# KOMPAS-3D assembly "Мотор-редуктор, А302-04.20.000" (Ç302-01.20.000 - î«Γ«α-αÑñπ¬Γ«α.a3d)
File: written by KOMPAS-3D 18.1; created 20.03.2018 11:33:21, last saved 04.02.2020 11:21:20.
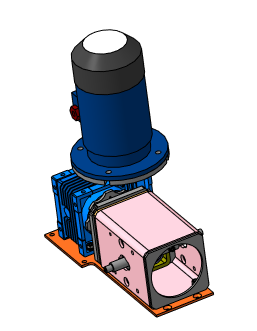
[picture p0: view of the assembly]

Document properties: Автор: Милов; Полное имя файла: D:\Мембранные насосы\Мембранный электропривод\А302-00.00.000 - ASTRA-302 (МЭ200) новая для Караби\3Д ПВХ\Отработка\А302-01.20.000 - Мотор-редуктор.a3d

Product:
- Part/product: Мотор-редуктор  | designation А302-04.20.000  | pos. 0
    Масса: 34.037
    Раздел спецификации: Сборочные единицы
    Форматы листов документа: 2xA3
    Примечание: @100~)2xA3
    source file: ..\..\А302-04.00.000 - Мембранный насос ASTRA-302-PP\А302-04.20.000 СБ - Мотор-редуктор.cdw
  - Component [standard]: Винт с цилиндрической головкой и шестигранным углублением под ключ ГОСТ Р ИСО 4762-М8 x 25-A2-70  | pos. 150  | Материал: Нержавеющая сталь (density 1000 kg/m3); Масса: 0.015; Раздел спецификации: Стандартные изделия; Рассекать на разрезах: no; additional columns: ГОСТ Р ИСО 4762-2012; М8 x 25 - A2-70
  - Component [standard]: Винт с цилиндрической головкой и шестигранным углублением под ключ ГОСТ Р ИСО 4762-М8 x 25-A2-70  | pos. 149  | Материал: Нержавеющая сталь (density 1000 kg/m3); Масса: 0.015; Раздел спецификации: Стандартные изделия; Рассекать на разрезах: no; additional columns: ГОСТ Р ИСО 4762-2012; М8 x 25 - A2-70
  - Component [standard]: Винт с цилиндрической головкой и шестигранным углублением под ключ ГОСТ Р ИСО 4762-М8 x 25-A2-70  | pos. 147  | Материал: Нержавеющая сталь (density 1000 kg/m3); Масса: 0.015; Раздел спецификации: Стандартные изделия; Рассекать на разрезах: no; additional columns: ГОСТ Р ИСО 4762-2012; М8 x 25 - A2-70
  - Component [standard]: Винт с цилиндрической головкой и шестигранным углублением под ключ ГОСТ Р ИСО 4762-М8 x 25-A2-70  | pos. 146  | Материал: Нержавеющая сталь (density 1000 kg/m3); Масса: 0.015; Раздел спецификации: Стандартные изделия; Рассекать на разрезах: no; additional columns: ГОСТ Р ИСО 4762-2012; М8 x 25 - A2-70
  - Component [standard]: Винт с цилиндрической головкой и шестигранным углублением под ключ ГОСТ Р ИСО 4762-М8 x 25-A2-70  | pos. 140  | Материал: Нержавеющая сталь (density 1000 kg/m3); Масса: 0.015; Раздел спецификации: Стандартные изделия; Рассекать на разрезах: no; additional columns: ГОСТ Р ИСО 4762-2012; М8 x 25 - A2-70
  - Component [standard]: Винт с цилиндрической головкой и шестигранным углублением под ключ ГОСТ Р ИСО 4762-М8 x 25-A2-70  | pos. 139  | Материал: Нержавеющая сталь (density 1000 kg/m3); Масса: 0.015; Раздел спецификации: Стандартные изделия; Рассекать на разрезах: no; additional columns: ГОСТ Р ИСО 4762-2012; М8 x 25 - A2-70
  - Component [standard]: Винт с цилиндрической головкой и шестигранным углублением под ключ ГОСТ Р ИСО 4762-М8 x 25-A2-70  | pos. 138  | Материал: Нержавеющая сталь (density 1000 kg/m3); Масса: 0.015; Раздел спецификации: Стандартные изделия; Рассекать на разрезах: no; additional columns: ГОСТ Р ИСО 4762-2012; М8 x 25 - A2-70
  - Component [standard]: Винт с цилиндрической головкой и шестигранным углублением под ключ ГОСТ Р ИСО 4762-М8 x 25-A2-70  | pos. 137  | Материал: Нержавеющая сталь (density 1000 kg/m3); Масса: 0.015; Раздел спецификации: Стандартные изделия; Рассекать на разрезах: no; additional columns: ГОСТ Р ИСО 4762-2012; М8 x 25 - A2-70
  - Component [standard]: Винт с цилиндрической головкой и шестигранным углублением под ключ ГОСТ Р ИСО 4762-М8 x 25-A2-70  | pos. 129  | Материал: Нержавеющая сталь (density 1000 kg/m3); Масса: 0.015; Раздел спецификации: Стандартные изделия; Рассекать на разрезах: no; additional columns: ГОСТ Р ИСО 4762-2012; М8 x 25 - A2-70
  - Component [standard]: Винт с цилиндрической головкой и шестигранным углублением под ключ ГОСТ Р ИСО 4762-М8 x 25-A2-70  | pos. 128  | Материал: Нержавеющая сталь (density 1000 kg/m3); Масса: 0.015; Раздел спецификации: Стандартные изделия; Рассекать на разрезах: no; additional columns: ГОСТ Р ИСО 4762-2012; М8 x 25 - A2-70
  - Component [standard]: Гайка М6-6H.21.12Х18Н10Т ГОСТ 5915-70  | qty 2  | Материал: Сталь 12Х18Н10Т ГОСТ 5632-72 (density 1000 kg/m3); Масса: 0.002573; Раздел спецификации: Стандартные изделия; Рассекать на разрезах: no
  - Component [standard]: Шайба 6 30Х13 019 ГОСТ 6402-70  | qty 2  | Материал: Сталь 30Х13 ГОСТ 5632-72 (density 1000 kg/m3); Масса: 0.000376; Раздел спецификации: Стандартные изделия; Рассекать на разрезах: no
  - Component [standard]: Шайба C.6.21 ГОСТ 11371-78  | qty 3  | Материал: Сталь 12Х18Н10Т ГОСТ 5632-72 (density 1000 kg/m3); Масса: 0.00099; Раздел спецификации: Стандартные изделия; Рассекать на разрезах: no
  - Component [standard]: Болт М6-6gx40 ГОСТ 7805-70  | qty 2  | Масса: 0.0112; Раздел спецификации: Стандартные изделия; Рассекать на разрезах: no
  - Component [standard]: Шайба C.6.21 ГОСТ 11371-78  | Материал: Сталь 20 ГОСТ 1050-2013 (density 1000 kg/m3); Масса: 0.00043; Раздел спецификации: Стандартные изделия; Рассекать на разрезах: no
  - Component [detail]: Вал  | designation А302-04.20.004  | pos. 3
      Материал: Сталь 40Х  ГОСТ 4543-71 (density 7825 kg/m3)
      Масса: 0.49487
      Раздел спецификации: Детали
      Форматы листов документа: A3
      Примечание: Заим.
      source file: ..\..\3Д\А302-00.20.004 - Вал.m3d, ..\..\А302-04.00.000 - Мембранный насос ASTRA-302-PP\А302-04.20.004 - Вал.cdw, ..\..\Чертежи ПВХ\А302-03.20.004 - Вал.cdw
  - Component [detail]: Эксцентрик  | designation А302-01.20.002  | pos. 5  | Материал: Сталь 40Х  ГОСТ 4543-71 (density 7825 kg/m3); Масса: 1.91612; Раздел спецификации: Детали; Форматы листов документа: A3; source file: ..\А302-01.20.002 - Эксцентрик.cdw, ..\А302-01.20.002 - Эксцентрик.m3d
  - Component [assembly]: Фланец  | designation А302-04.35.000  | pos. 1  | Масса: 8.08129; Раздел спецификации: Сборочные единицы; Форматы листов документа: A2; source file: ..\..\А302-04.00.000 - Мембранный насос ASTRA-302-PP Чертежи\А302-04.35.000 - Фланец.cdw, ..\..\А302-04.00.000 - Мембранный насос ASTRA-302-PP\А302-04.35.000 - Фланец.cdw, ..\А302-01.35.000 - Фланец.a3d
  - Component [detail]: Основание  | designation А302-04.20.001  | pos. 4  | Материал: Сталь 20  ГОСТ 1050-2013 (density 7820 kg/m3); Масса: 2.48727; Раздел спецификации: Детали; Форматы листов документа: A3
  - Component [detail]: FB 063  | pos. 6  | Масса: 1.71461; Раздел спецификации: Детали; source file: ..\FB 063 .m3d
  - Component [detail]: Подшипник 80х40х18 6208-2RS1 SKF  | pos. 54  | Масса: 0.504792; Раздел спецификации: Стандартные изделия; source file: ..\..\..\..\..\1 ПКИ 3D\1 Крепеж стандартный\Подшипник\Подшипник 80х40х18 6208-2RS1 SKF.m3d
  - Component [standard]: Кольцо A40.65Г ГОСТ 13942-86  | pos. 51  | Материал: Сталь 65Г ГОСТ 14959-79 (density 1000 kg/m3); Масса: 0.007267; Раздел спецификации: Стандартные изделия; additional columns: Сталь 65Г ГОСТ 14959-79
- Part/product: Мотор-редуктор  | designation А302-02.20.000  | pos. 0
    Масса: 27.8186
    Раздел спецификации: Сборочные единицы
    Форматы листов документа: 2xA3
    Примечание: @100~)2xA3
  - Component [detail]: Основание  | designation А302-01.20.001  | pos. 4  | Материал: Сталь 20  ГОСТ 1050-2013 (density 7820 kg/m3); Масса: 2.48169; Раздел спецификации: Детали; Форматы листов документа: A3; source file: ..\..\А302-04.00.000 - Мембранный насос ASTRA-302-PP\А302-04.20.001 - Основание.cdw, ..\А302-01.20.001 - Основание.cdw, ..\А302-01.20.001 - Основание.m3d
  - Component [assembly]: Фланец  | designation А302-01.35.000  | pos. 1  | Масса: 8.26617; Раздел спецификации: Сборочные единицы; Форматы листов документа: 2xA3; Примечание: @100~)2xA3; source file: ..\А302-01.35.000 - Фланец.a3d, ..\А302-01.35.000 - Фланец.cdw
  - Component [detail]: Эксцентрик  | designation А302-01.20.002  | pos. 5  | Материал: Сталь 40Х  ГОСТ 4543-71 (density 7825 kg/m3); Масса: 1.91612; Раздел спецификации: Детали; Форматы листов документа: A3; source file: ..\А302-01.20.002 - Эксцентрик.cdw, ..\А302-01.20.002 - Эксцентрик.m3d
  - Component [detail]: Вал  | designation А302-04.20.004  | pos. 3
      Материал: Сталь 40Х  ГОСТ 4543-71 (density 7825 kg/m3)
      Масса: 0.49487
      Раздел спецификации: Детали
      Форматы листов документа: A3
      Примечание: Заим.
      source file: ..\..\3Д\А302-00.20.004 - Вал.m3d, ..\..\А302-04.00.000 - Мембранный насос ASTRA-302-PP\А302-04.20.004 - Вал.cdw, ..\..\Чертежи ПВХ\А302-03.20.004 - Вал.cdw
- Part/product: Мотор-редуктор  | designation А302-01.20.000  | pos. 0
    Масса: 27.8253
    Раздел спецификации: Сборочные единицы
    Форматы листов документа: 2xA3
    Примечание: @100~)2xA3
    source file: ..\А302-01.20.000 - Мотор-редуктор.cdw
  - Component [standard]: Гайка М8-6H.21.12Х18Н10Т ГОСТ 5915-70  | qty 6  | Материал: Сталь 12Х18Н10Т ГОСТ 5632-72 (density 1000 kg/m3); Масса: 0.005548; Раздел спецификации: Стандартные изделия; source file: C:\Program Files\ASCON\KOMPAS-3D v18\Libs\PartLib\DATA\VAULT\methods\kompas\3d\PLib_Nut_OST92_900.m3d
  - Component [standard]: Шайба C.8.21 ГОСТ 11371-78  | qty 8  | pos. 18  | Материал: Сталь 12Х18Н10Т ГОСТ 5632-72 (density 1000 kg/m3); Масса: 0.001725; Раздел спецификации: Стандартные изделия; additional columns: Сталь 12Х18Н10Т ГОСТ 5632-72; source file: C:\Program Files\ASCON\KOMPAS-3D v18\Libs\PartLib\DATA\VAULT\methods\kompas\3d\PLib_Washer_1_712.m3d
  - Component [standard]: Шайба 8 30Х13 019 ГОСТ 6402-70  | qty 14  | Материал: Сталь 30Х13 ГОСТ 5632-72 (density 1000 kg/m3); Масса: 0.001034; Раздел спецификации: Стандартные изделия; source file: C:\Program Files\ASCON\KOMPAS-3D v18\Libs\PartLib\DATA\VAULT\methods\kompas\3d\PLib_Washer_2_712.m3d
  - Component [standard]: Винт с цилиндрической головкой и шестигранным углублением под ключ ГОСТ Р ИСО 4762 - М8 x 25 - A2-70  | qty 10  | Материал: Нержавеющая сталь (density 1000 kg/m3); Масса: 0.015; Раздел спецификации: Стандартные изделия; additional columns: ГОСТ Р ИСО 4762-2012; source file: C:\Program Files\ASCON\KOMPAS-3D v18\Libs\PartLib\DATA\VAULT\methods\kompas\3d\PLib_Screw_DIN_7984_1500.m3d
  - Component [standard]: Шайба C.8.21 ГОСТ 11371-78  | qty 12  | Материал: Сталь 12Х18Н10Т ГОСТ 5632-72 (density 1000 kg/m3); Масса: 0.001725; Раздел спецификации: Стандартные изделия; source file: C:\Program Files\ASCON\KOMPAS-3D v18\Libs\PartLib\DATA\VAULT\methods\kompas\3d\PLib_Washer_1_712.m3d
  - Component [standard]: Шпонка 8x7x90 ГОСТ 23360-78  | Масса: 0.03854; Раздел спецификации: Стандартные изделия; source file: C:\Program Files\ASCON\KOMPAS-3D v18\Libs\PartLib\DATA\VAULT\methods\kompas\3d\PLib_Key_prismatic_712.m3d
  - Component [standard]: Винт с цилиндрической головкой и шестигранным углублением под ключ ГОСТ Р ИСО 4762 - М8 x 35 - A2-70  | qty 4  | Материал: Нержавеющая сталь (density 1000 kg/m3); Масса: 0.0189; Раздел спецификации: Стандартные изделия; additional columns: ГОСТ Р ИСО 4762-2012; source file: C:\Program Files\ASCON\KOMPAS-3D v18\Libs\PartLib\DATA\VAULT\methods\kompas\3d\PLib_Screw_DIN_7984_1500.m3d
  - Component [standard]: Гайка М5-6H.5.019 ГОСТ 5915-70  | qty 2  | Масса: 0.00144; Раздел спецификации: Стандартные изделия; source file: C:\Program Files\ASCON\KOMPAS-3D v18\Libs\PartLib\DATA\VAULT\methods\kompas\3d\PLib_Nut_OST92_900.m3d
  - Component [standard]: Шайба 5 30Х13 019 ГОСТ 6402-70  | qty 2  | Материал: Сталь 30Х13 ГОСТ 5632-72 (density 1000 kg/m3); Масса: 0.000228; Раздел спецификации: Стандартные изделия; source file: C:\Program Files\ASCON\KOMPAS-3D v18\Libs\PartLib\DATA\VAULT\methods\kompas\3d\PLib_Washer_2_712.m3d
  - Component [standard]: Шайба C.5.04.019 ГОСТ 11371-78  | qty 4  | Материал: Сталь 20 ГОСТ 1050-2013 (density 1000 kg/m3); Масса: 0.00043; Раздел спецификации: Стандартные изделия; source file: C:\Program Files\ASCON\KOMPAS-3D v18\Libs\PartLib\DATA\VAULT\methods\kompas\3d\PLib_Washer_1_712.m3d
  - Component [standard]: Болт М5-6gx35.58.019 ГОСТ 7805-70  | qty 2  | Материал: Сталь 20 ГОСТ 1050-2013 (density 1000 kg/m3); Масса: 0.006685; Раздел спецификации: Стандартные изделия; source file: C:\Program Files\ASCON\KOMPAS-3D v18\Libs\PartLib\DATA\VAULT\methods\kompas\3d\PLib_Bolt_1_900.m3d
  - Component [detail]: Ползун  | designation А302-00.20.003  | pos. 2
      Материал: Полиамид П-12Б-20  ТУ 6-05-898-73 (density 1020 kg/m3)
      Масса: 0.0527789
      Раздел спецификации: Детали
      Форматы листов документа: A3
      Примечание: Заим.
      source file: ..\..\3Д\А302-00.20.003 - Ползун.m3d
  - Component [detail]: Вал  | designation А302-02.20.004  | pos. 3
      Материал: Сталь 40Х  ГОСТ 4543-71 (density 7825 kg/m3)
      Масса: 0.365977
      Раздел спецификации: Детали
      Форматы листов документа: A3
      Примечание: Заим.
      source file: ..\..\3Д\А302-00.20.004 - Вал.m3d, ..\..\Чертежи ПВХ\А302-02.20.004 - Вал.cdw
  - Component [detail]: Подшипник 52х25х15 62052RSH SKF  | pos. 21  | Масса: 0.182287; Раздел спецификации: Стандартные изделия; source file: ..\..\..\..\..\1 ПКИ 3D\1 Крепеж стандартный\Подшипник\Подшипник 52х25х15 62052RSH SKF.m3d
  - Component [standard]: Кольцо A25.65Г ГОСТ 13942-86  | qty 3  | Материал: Сталь 65Г ГОСТ 14959-79 (density 1000 kg/m3); Масса: 0.002684; Раздел спецификации: Стандартные изделия; source file: C:\Program Files\ASCON\KOMPAS-3D v18\Libs\PartLib\DATA\VAULT\methods\kompas\3d\PLib_Check_spring_rings_GOST_13942_911.m3d
  - Component [detail]: Эксцентрик  | designation А302-01.20.002  | pos. 5  | Материал: Сталь 40Х  ГОСТ 4543-71 (density 7825 kg/m3); Масса: 1.91612; Раздел спецификации: Детали; Форматы листов документа: A3; source file: ..\А302-01.20.002 - Эксцентрик.cdw, ..\А302-01.20.002 - Эксцентрик.m3d
  - Component [assembly]: Фланец  | designation А302-01.35.000  | pos. 1  | Масса: 8.26617; Раздел спецификации: Сборочные единицы; Форматы листов документа: 2xA3; Примечание: @100~)2xA3; source file: ..\А302-01.35.000 - Фланец.a3d, ..\А302-01.35.000 - Фланец.cdw
  - Component [detail]: Основание  | designation А302-01.20.001  | pos. 4  | Материал: Сталь 20  ГОСТ 1050-2013 (density 7820 kg/m3); Масса: 2.48169; Раздел спецификации: Детали; Форматы листов документа: A3; source file: ..\..\А302-04.00.000 - Мембранный насос ASTRA-302-PP\А302-04.20.001 - Основание.cdw, ..\А302-01.20.001 - Основание.cdw, ..\А302-01.20.001 - Основание.m3d
  - Component [assembly]: Мотор-редуктор / NMRV063 N P(кВт) V5 / P(мощн./дв.), i(передат. отн.) см. заказ  | pos. 22  | Масса: 18.2; Раздел спецификации: Прочие изделия; Примечание: Двигатель / 1400 об/мин / N=1400/i; source file: ..\..\..\..\..\1 ПКИ 3D\Редуктора NMRW\Редукторы\Червячный мотор-редуктор NMRV063 АИР80.a3d
  - Component: Винт с цилиндрической головкой и / шестигранным углублением под ключ  / ГОСТ Р ИСО  4762-М8 x 20-6.8-A9J  | pos. 7  | Масса: 0.0134; Раздел спецификации: Стандартные изделия; additional columns: Сталь
  - Component: Шайба C.8.04.019 ГОСТ 11371-78  | qty 4  | pos. 19  | Масса: 0.001725; Раздел спецификации: Стандартные изделия; additional columns: Сталь 20 ГОСТ 1050-2013
  - Component: Винт с цилиндрической головкой /  и шестигранным углублением под ключ  / ГОСТ Р ИСО  4762-М8 x 35-A2-70  | pos. 10  | Масса: 0.0189; Раздел спецификации: Стандартные изделия; additional columns: Сталь
  - Component: Винт с цилиндрической головкой и шестигранным углублением под ключ ГОСТ Р ИСО  4762-М8 x 35-6.8-A9J  | pos. 10  | Масса: 0.0189; Раздел спецификации: Стандартные изделия; additional columns: Сталь
  - Component: Винт с цилиндрической головкой и  / шестигранным углублением под ключ  / ГОСТ Р ИСО  4762-М8 x 25-A2-70  | pos. 8  | Масса: 0.015; Раздел спецификации: Стандартные изделия; additional columns: Нержавеющая сталь
  - Component: Винт с цилиндрической головкой и шестигранным углублением под ключ ГОСТ Р ИСО  4762-М8 x 25-A2-70  | pos. 8  | Масса: 0.015; Раздел спецификации: Стандартные изделия; additional columns: Нержавеющая сталь
  - Component: Шпонка 8 x 7 x 90 ГОСТ 23360-78  | pos. 20  | Масса: 0.03854; Раздел спецификации: Стандартные изделия
  - Component: Винт с цилиндрической головкой /  и шестигранным углублением под ключ  / ГОСТ Р ИСО  4762-М8 x 35-A2-70  | pos. 9  | Масса: 0.0189; Раздел спецификации: Стандартные изделия; additional columns: Нержавеющая сталь
- Part/product: Мотор-редуктор  | designation А302-04.20.000-X  | pos. 0
    Масса: 33.9715
    Раздел спецификации: Сборочные единицы
    Форматы листов документа: 2xA3
    Примечание: @100~)2xA3
    source file: ..\..\Разное\А302-04.00.000-X - Мембранный насос ASTRA-302-PP заказ клиента 1126\А302-04.20.000-X СБ - Мотор-редуктор.cdw
  - Component: Screw DIN 6912-М6 x 50  | pos. 192  | Материал: Не определено; Масса: 0.0115; Раздел спецификации: Стандартные изделия
  - Component [standard]: Screw DIN 6912 - М6 x 50  | qty 2  | pos. 190  | Материал: Не определено (density 1000 kg/m3); Масса: 0.0115; Раздел спецификации: Стандартные изделия; Рассекать на разрезах: no
  - Component [standard]: Кольцо A40.65Г ГОСТ 13942-86  | pos. 51  | Материал: Сталь 65Г ГОСТ 14959-79 (density 1000 kg/m3); Масса: 0.007267; Раздел спецификации: Стандартные изделия; additional columns: Сталь 65Г ГОСТ 14959-79
  - Component [detail]: Основание  | designation А302-04.20.001  | pos. 4  | Материал: Сталь 20  ГОСТ 1050-2013 (density 7820 kg/m3); Масса: 2.48727; Раздел спецификации: Детали; Форматы листов документа: A3
  - Component [assembly]: Фланец  | designation А302-04.35.000  | pos. 1  | Масса: 8.08129; Раздел спецификации: Сборочные единицы; Форматы листов документа: A2; source file: ..\..\А302-04.00.000 - Мембранный насос ASTRA-302-PP Чертежи\А302-04.35.000 - Фланец.cdw, ..\..\А302-04.00.000 - Мембранный насос ASTRA-302-PP\А302-04.35.000 - Фланец.cdw, ..\А302-01.35.000 - Фланец.a3d
  - Component [detail]: Эксцентрик  | designation А302-01.20.002  | pos. 5  | Материал: Сталь 40Х  ГОСТ 4543-71 (density 7825 kg/m3); Масса: 1.91612; Раздел спецификации: Детали; Форматы листов документа: A3; source file: ..\А302-01.20.002 - Эксцентрик.cdw, ..\А302-01.20.002 - Эксцентрик.m3d
  - Component [detail]: Вал  | designation А302-04.20.004  | pos. 3
      Материал: Сталь 40Х  ГОСТ 4543-71 (density 7825 kg/m3)
      Масса: 0.49487
      Раздел спецификации: Детали
      Форматы листов документа: A3
      Примечание: Заим.
      source file: ..\..\3Д\А302-00.20.004 - Вал.m3d, ..\..\А302-04.00.000 - Мембранный насос ASTRA-302-PP\А302-04.20.004 - Вал.cdw, ..\..\Чертежи ПВХ\А302-03.20.004 - Вал.cdw
  - Component [standard]: Шайба C.6.21 ГОСТ 11371-78  | qty 3  | Материал: Сталь 12Х18Н10Т ГОСТ 5632-72 (density 1000 kg/m3); Масса: 0.00099; Раздел спецификации: Стандартные изделия; Рассекать на разрезах: no
  - Component [standard]: Шайба 6 30Х13 019 ГОСТ 6402-70  | qty 2  | Материал: Сталь 30Х13 ГОСТ 5632-72 (density 1000 kg/m3); Масса: 0.000376; Раздел спецификации: Стандартные изделия; Рассекать на разрезах: no
  - Component [standard]: Гайка М6-6H.21.12Х18Н10Т ГОСТ 5915-70  | qty 2  | Материал: Сталь 12Х18Н10Т ГОСТ 5632-72 (density 1000 kg/m3); Масса: 0.002573; Раздел спецификации: Стандартные изделия; Рассекать на разрезах: no
  - Component [standard]: Шайба C.6.21 ГОСТ 11371-78  | Материал: Сталь 20 ГОСТ 1050-2013 (density 1000 kg/m3); Масса: 0.00043; Раздел спецификации: Стандартные изделия; Рассекать на разрезах: no
  - Component [standard]: Винт с цилиндрической головкой и шестигранным углублением под ключ ГОСТ Р ИСО 4762-М8 x 25-A2-70  | pos. 128  | Материал: Нержавеющая сталь (density 1000 kg/m3); Масса: 0.015; Раздел спецификации: Стандартные изделия; Рассекать на разрезах: no; additional columns: ГОСТ Р ИСО 4762-2012; М8 x 25 - A2-70
  - Component [standard]: Винт с цилиндрической головкой и шестигранным углублением под ключ ГОСТ Р ИСО 4762-М8 x 25-A2-70  | pos. 129  | Материал: Нержавеющая сталь (density 1000 kg/m3); Масса: 0.015; Раздел спецификации: Стандартные изделия; Рассекать на разрезах: no; additional columns: ГОСТ Р ИСО 4762-2012; М8 x 25 - A2-70
  - Component [standard]: Винт с цилиндрической головкой и шестигранным углублением под ключ ГОСТ Р ИСО 4762-М8 x 25-A2-70  | pos. 137  | Материал: Нержавеющая сталь (density 1000 kg/m3); Масса: 0.015; Раздел спецификации: Стандартные изделия; Рассекать на разрезах: no; additional columns: ГОСТ Р ИСО 4762-2012; М8 x 25 - A2-70
  - Component [standard]: Винт с цилиндрической головкой и шестигранным углублением под ключ ГОСТ Р ИСО 4762-М8 x 25-A2-70  | pos. 138  | Материал: Нержавеющая сталь (density 1000 kg/m3); Масса: 0.015; Раздел спецификации: Стандартные изделия; Рассекать на разрезах: no; additional columns: ГОСТ Р ИСО 4762-2012; М8 x 25 - A2-70
  - Component [standard]: Винт с цилиндрической головкой и шестигранным углублением под ключ ГОСТ Р ИСО 4762-М8 x 25-A2-70  | pos. 139  | Материал: Нержавеющая сталь (density 1000 kg/m3); Масса: 0.015; Раздел спецификации: Стандартные изделия; Рассекать на разрезах: no; additional columns: ГОСТ Р ИСО 4762-2012; М8 x 25 - A2-70
  - Component [standard]: Винт с цилиндрической головкой и шестигранным углублением под ключ ГОСТ Р ИСО 4762-М8 x 25-A2-70  | pos. 140  | Материал: Нержавеющая сталь (density 1000 kg/m3); Масса: 0.015; Раздел спецификации: Стандартные изделия; Рассекать на разрезах: no; additional columns: ГОСТ Р ИСО 4762-2012; М8 x 25 - A2-70
  - Component [standard]: Винт с цилиндрической головкой и шестигранным углублением под ключ ГОСТ Р ИСО 4762-М8 x 25-A2-70  | pos. 146  | Материал: Нержавеющая сталь (density 1000 kg/m3); Масса: 0.015; Раздел спецификации: Стандартные изделия; Рассекать на разрезах: no; additional columns: ГОСТ Р ИСО 4762-2012; М8 x 25 - A2-70
  - Component [standard]: Винт с цилиндрической головкой и шестигранным углублением под ключ ГОСТ Р ИСО 4762-М8 x 25-A2-70  | pos. 147  | Материал: Нержавеющая сталь (density 1000 kg/m3); Масса: 0.015; Раздел спецификации: Стандартные изделия; Рассекать на разрезах: no; additional columns: ГОСТ Р ИСО 4762-2012; М8 x 25 - A2-70
  - Component [standard]: Винт с цилиндрической головкой и шестигранным углублением под ключ ГОСТ Р ИСО 4762-М8 x 25-A2-70  | pos. 149  | Материал: Нержавеющая сталь (density 1000 kg/m3); Масса: 0.015; Раздел спецификации: Стандартные изделия; Рассекать на разрезах: no; additional columns: ГОСТ Р ИСО 4762-2012; М8 x 25 - A2-70
  - Component [standard]: Винт с цилиндрической головкой и шестигранным углублением под ключ ГОСТ Р ИСО 4762-М8 x 25-A2-70  | pos. 150  | Материал: Нержавеющая сталь (density 1000 kg/m3); Масса: 0.015; Раздел спецификации: Стандартные изделия; Рассекать на разрезах: no; additional columns: ГОСТ Р ИСО 4762-2012; М8 x 25 - A2-70
  - Component [detail]: Шайба 43х25х3.3  | pos. 189  | Масса: 0.0249222; Раздел спецификации: Детали; source file: ..\..\Разное\А302-04.00.000-X - Мембранный насос ASTRA-302-PP заказ клиента 1126\Шайба 43х25х3.3.m3d
- Part/product: Мотор-редуктор  | designation А302-01.20.000-test  | pos. 0
    Масса: 27.8253
    Раздел спецификации: Сборочные единицы
    Форматы листов документа: 2xA3
    Примечание: @100~)2xA3
  - Component [assembly]: Фланец  | designation А302-01.35.000  | pos. 1  | Масса: 8.26617; Раздел спецификации: Сборочные единицы; Форматы листов документа: 2xA3; Примечание: @100~)2xA3; source file: ..\А302-01.35.000 - Фланец.a3d

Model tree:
1. Массив по образцу:1
2. Экземпляр ( 1 )
3. Экземпляр ( 2 )
4. Массив по сетке:1  (4 pattern instances)
     Шаг 1 = 130; Угол раствора = 90; Шаг 2 = 85
5. Массив по сетке:2  (2 pattern instances)
     Наклон = 180; Шаг 1 = 100; Угол раствора = 90
6. Массив по концентрической сетке:2  (with: Операция без истории:2)  (8 pattern instances)
     Шаг 2 = 360
7. Сечение поверхностью:2
8. Сечение поверхностью:1  (with: Вырезать элемент выдавливания:3, Операция без истории:2, Вырезать элемент выдавливания:4, Операция без истории:4, Операция вращения:1, Операция выдавливания:1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)  (labels: Отверстие в ушке d4; Операция выдавливания:1; Операция выдавливания:1; Операция выдавливания:1)
9. Эскиз:1  (with: Вырезать элемент выдавливания:2, Вырез в листовом теле:1)
10. Элемент выдавливания:1
     Расстояние 2 = 10
11. Эскиз:3  (with: Chamfer:1)
12. Эскиз:4  (with: Chamfer:1)
13. Элемент выдавливания:2
     Расстояние 1 = 5
14. Эскиз:5  (with: Chamfer:1, Curvature:5)
15. Элемент выдавливания:3
     Расстояние 1 = 5

Expressions: A2-70
Referenced files in D:\1 ПКИ 3D\Редуктора NMRW\Редукторы\: Червячный мотор-редуктор NMRV063 АИР80.a3d
Referenced files in D:\Мембранные насосы\Мембранный электропривод\А302-00.00.000 - ASTRA-302 (МЭ200) новая для Караби\3Д ПВХ\: А302-01.20.001 - Основание.m3d, А302-01.20.001 - Основание.cdw, А302-01.35.000 - Фланец.a3d, А302-01.35.000 - Фланец.cdw, А302-01.20.002 - Эксцентрик.m3d, А302-01.20.002 - Эксцентрик.cdw, FB 063 .m3d, А302-01.20.000 - Мотор-редуктор.cdw
Referenced files in D:\1 ПКИ 3D\1 Крепеж стандартный\Подшипник\: Подшипник 52х25х15 62052RSH SKF.m3d, Подшипник 80х40х18 6208-2RS1 SKF.m3d
Referenced files in D:\Мембранные насосы\Мембранный электропривод\А302-00.00.000 - ASTRA-302 (МЭ200) новая для Караби\3Д\: А302-00.20.004 - Вал.m3d, А302-00.20.003 - Ползун.m3d
Referenced files in D:\Мембранные насосы\Мембранный электропривод\А302-00.00.000 - ASTRA-302 (МЭ200) новая для Караби\Чертежи ПВХ\: А302-02.20.004 - Вал.cdw
Referenced files in C:\Program Files\ASCON\KOMPAS-3D v18\Libs\PartLib\DATA\VAULT\methods\kompas\3d\: PLib_Washer_1_712.m3d, PLib_Check_spring_rings_GOST_13942_911.m3d, PLib_Bolt_1_900.m3d, PLib_Washer_2_712.m3d, PLib_Nut_OST92_900.m3d, PLib_Screw_DIN_7984_1500.m3d, PLib_Key_prismatic_712.m3d
Referenced files in D:\Мембранные насосы\Мембранный электропривод\А302-00.00.000 - ASTRA-302 (МЭ200) новая для Караби\3Д ПВХ\Отработка\..\..\Чертежи ПВХ\: А302-03.20.004 - Вал.cdw
Referenced files in D:\Мембранные насосы\Мембранный электропривод\А302-00.00.000 - ASTRA-302 (МЭ200) новая для Караби\3Д ПВХ\Отработка\..\..\А302-04.00.000 - Мембранный насос ASTRA-302-PP\: А302-04.20.004 - Вал.cdw, А302-04.35.000 - Фланец.cdw
Referenced files in D:\Мембранные насосы\Мембранный электропривод\А302-00.00.000 - ASTRA-302 (МЭ200) новая для Караби\3Д ПВХ\Отработка\..\: А302-01.20.002 - Эксцентрик.cdw
Referenced files in D:\Мембранные насосы\Мембранный электропривод\А302-00.00.000 - ASTRA-302 (МЭ200) новая для Караби\3Д ПВХ\Отработка\..\..\А302-04.00.000 - Мембранный насос ASTRA-302-PP Чертежи\: А302-04.35.000 - Фланец.cdw
Referenced files in D:\Мембранные насосы\Мембранный электропривод\А302-00.00.000 - ASTRA-302 (МЭ200) новая для Караби\3Д\..\Чертежи ПВХ\: А302-03.20.004 - Вал.cdw
Referenced files in D:\Мембранные насосы\Мембранный электропривод\А302-00.00.000 - ASTRA-302 (МЭ200) новая для Караби\А302-04.00.000 - Мембранный насос ASTRA-302-PP Чертежи\: А302-04.35.000 - Фланец.cdw
Referenced files in D:\Мембранные насосы\Мембранный электропривод\А302-00.00.000 - ASTRA-302 (МЭ200) новая для Караби\А302-04.00.000 - Мембранный насос ASTRA-302-PP\: А302-04.35.000 - Фланец.cdw
Referenced files in D:\Мембранные насосы\Мембранный электропривод\А302-00.00.000 - ASTRA-302 (МЭ200) новая для Караби\Разное\А302-04.00.000-X - Мембранный насос ASTRA-302-PP заказ клиента 1126\: Шайба 43х25х3.3.m3d
Referenced files in C:\Program Files\ASCON\KOMPAS-3D V16\Libs\PartLib\DATA\vault\Methods\Kompas\3D\: PLib_Check_spring_rings_GOST_13942_911.m3d, PLib_Washer_1_712.m3d, PLib_Screw_DIN_7984_1500.m3d
Referenced files in C:\Program Files\ASCON\KOMPAS-3D V16\Libs\PartLib\DATA\VAULT\Methods\kompas\3d\: PLib_Bolt_1_900.m3d, PLib_Washer_2_712.m3d, PLib_Nut_OST92_900.m3d
Referenced files in D:\Мембранные насосы\Мембранный электропривод\А302-00.00.000 - ASTRA-302 (МЭ200)\3Д\: А302-00.20.003 - Ползун.m3d, А302-00.20.004 - Вал.m3d
Referenced files in C:\Program Files\ASCON\KOMPAS-3D v18\Libs\PARTLib\DATA\vault\Methods\Kompas\3D\: PLib_Washer_2_712.m3d, PLib_Nut_OST92_900.m3d, PLib_Screw_DIN_6912_1500.m3d
Referenced files in D:\Мембранные насосы\Мембранный электропривод\А302-00.00.000 - ASTRA-302 (МЭ200)\3Д ПВХ\: FB 063 .m3d, А302-01.35.000 - Фланец.a3d, А302-01.20.001 - Основание.m3d, А302-01.20.002 - Эксцентрик.m3d
Referenced files in D:\Мембранные насосы\Мембранный электропривод\А302-00.00.000 - ASTRA-302 (МЭ200)\Разное\А302-04.00.000-X - Мембранный насос ASTRA-302-PP заказ клиента 1126\: Шайба 43х25х3.3.m3d
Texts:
  Крепежное изделие ГОСТ
  3D_Doc-graphic.lyt,1.000000-4294967295-222156129657
  3D_Doc-graphic.lyt,1.000000-4294967295-222156129757
  3D_Doc-graphic.lyt,1.000000-4294967295-222156129857
  3D_Doc-graphic.lyt,1.000000-4294967295-222156129957
  3D_Doc-graphic.lyt,1.000000-4294967295-222156130057
  3D_Doc-graphic.lyt,1.000000-4294967295-222156130157
  3D_Doc-graphic.lyt,1.000000-4294967295-222156130257
  3D_Doc-graphic.lyt,1.000000-4294967295-222156130357
  3D_Doc-graphic.lyt,1.000000-4294967295-222156130457
  Винт с цилиндрической головкой и
  шестигранным углублением под ключ
  ГОСТ Р ИСО  4762-М8 x 20-6.8-A9J
  Винт с цилиндрической головкой и шестигранным углублением под ключ
  3D_Doc-graphic.lyt,1.000000-4294967295-222156130557
  3D_Doc-graphic.lyt,1.000000-4294967295-222156130657
  3D_Doc-graphic.lyt,1.000000-4294967295-222156130757
  Винт с цилиндрической головкой
  и шестигранным углублением под ключ
  ГОСТ Р ИСО  4762-М8 x 35-A2-70
  3D_Doc-graphic.lyt,1.000000-4294967295-222156130857
  3D_Doc-graphic.lyt,1.000000-4294967295-222156130957
  3D_Doc-graphic.lyt,1.000000-4294967295-222156131057
  3D_Doc-graphic.lyt,1.000000-4294967295-222156131157
  3D_Doc-graphic.lyt,1.000000-4294967295-222156131257
  3D_Doc-graphic.lyt,1.000000-4294967295-222156131357
  3D_Doc-graphic.lyt,1.000000-4294967295-222156131457
  3D_Doc-graphic.lyt,1.000000-4294967295-222156131557
  3D_Doc-graphic.lyt,1.000000-4294967295-222156132357
  ГОСТ Р ИСО  4762-М8 x 25-A2-70
  3D_Doc-graphic.lyt,1.000000-4294967295-222156132557
  3D_Doc-graphic.lyt,1.000000-4294967295-222156132657
  3D_Doc-graphic.lyt,1.000000-4294967295-222156132757
  3D_Doc-graphic.lyt,1.000000-4294967295-222156132857
  3D_Doc-graphic.lyt,1.000000-4294967295-222156133857
  3D_Doc-graphic.lyt,1.000000-4294967295-222156133957
  3D_Doc-graphic.lyt,1.000000-4294967295-222156134057
  3D_Doc-graphic.lyt,1.000000-4294967295-222156134157
  3D_Doc-graphic.lyt,1.000000-4294967295-222156134257
  3D_Doc-graphic.lyt,1.000000-4294967295-222156134757
  NMRV063 N P(кВт) V5
  P(мощн./дв.), i(передат. отн.) см. заказ
  Двигатель / 1400 об/мин / N=1400/i
  @100~)2xA3
  ГОСТ Р ИСО
  Точка начала. Х
  Точка начала. Y
  Точка начала. Z
  Isp3
  hole1
  hole2
  bcut1
  hcut1
  cut1
  skr2
  skr1
  Круглый торец_1
  Круглый торец_2
  Призма-исп.1
  Кольцо A25.65Г ГОСТ 13942-86 (1)
  Кольцо A25.65Г ГОСТ 13942-86 (2)
  Кольцо A25.65Г ГОСТ 13942-86 (3)
  Шайба C.6.21 ГОСТ 11371-78 (1)
  Болт М6-6gx40 ГОСТ 7805-70 (1)
  Шайба C.6.21 ГОСТ 11371-78 (2)
  Шайба 6 30Х13 019 ГОСТ 6402-70 (1)
  Гайка М6-6H.21.12Х18Н10Т ГОСТ 5915-70 (1)
  Шайба C.8.21 ГОСТ 11371-78 (1)
  Шайба C.8.21 ГОСТ 11371-78 (2)
  Винт с цилиндрической головкой и шестигранным углублением под ключ ГОСТ Р ИСО 4762 - М8 x 25 - A2-70 (1)
  Шайба 8 30Х13 019 ГОСТ 6402-70 (1)
  Гайка М8-6H.21.12Х18Н10Т ГОСТ 5915-70 (1)
  Шайба C.8.21 ГОСТ 11371-78 (9)
  Шайба C.8.21 ГОСТ 11371-78 (10)
  Винт с цилиндрической головкой и шестигранным углублением под ключ ГОСТ Р ИСО 4762 - М8 x 25 - A2-70 (5)
  Шайба 8 30Х13 019 ГОСТ 6402-70 (5)
  Гайка М8-6H.21.12Х18Н10Т ГОСТ 5915-70 (2)
  FB 063  FB 063
  Шайба C.8.21 ГОСТ 11371-78 (13)
  Шайба C.8.21 ГОСТ 11371-78 (14)
  Винт с цилиндрической головкой и шестигранным углублением под ключ ГОСТ Р ИСО 4762-М8 x 25-A2-70 (7)
  Винт с цилиндрической головкой и шестигранным углублением под ключ ГОСТ Р ИСО 4762-М8 x 25-A2-70 (8)
  Шайба C.8.21 ГОСТ 11371-78 (15)
  Шайба C.8.21 ГОСТ 11371-78 (16)
  Шайба C.8.21 ГОСТ 11371-78 (17)
  Шайба C.8.21 ГОСТ 11371-78 (18)
  Винт с цилиндрической головкой и шестигранным углублением под ключ ГОСТ Р ИСО 4762-М8 x 25-A2-70 (9)
  Винт с цилиндрической головкой и шестигранным углублением под ключ ГОСТ Р ИСО 4762-М8 x 25-A2-70 (10)
  Винт с цилиндрической головкой и шестигранным углублением под ключ ГОСТ Р ИСО 4762-М8 x 25-A2-70 (11)
  Винт с цилиндрической головкой и шестигранным углублением под ключ ГОСТ Р ИСО 4762-М8 x 25-A2-70 (12)
  Шайба C.8.21 ГОСТ 11371-78 (19)
  Шайба C.8.21 ГОСТ 11371-78 (20)
  Шайба C.8.21 ГОСТ 11371-78 (21)
  Шайба C.8.21 ГОСТ 11371-78 (22)
  Винт с цилиндрической головкой и шестигранным углублением под ключ ГОСТ Р ИСО 4762-М8 x 25-A2-70 (13)
  Винт с цилиндрической головкой и шестигранным углублением под ключ ГОСТ Р ИСО 4762-М8 x 25-A2-70 (14)
  Винт с цилиндрической головкой и шестигранным углублением под ключ ГОСТ Р ИСО 4762-М8 x 25-A2-70 (15)
  Винт с цилиндрической головкой и шестигранным углублением под ключ ГОСТ Р ИСО 4762-М8 x 25-A2-70 (16)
